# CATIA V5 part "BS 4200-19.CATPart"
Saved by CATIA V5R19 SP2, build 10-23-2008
Part number: BS 4200-19
Bounding box of the stored display mesh (mm): x -47.487 to 47.487, y -47.487 to 47.487, z 0 to 103
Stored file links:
  C:\Users\Bora\Desktop\3D Katı model\BS serisi\BS 4200\BS 4200-19.CATPart
  C:\Program Files\Dassault Systemes\B19\intel_a\reffiles\standard\MetricThickPitch.txt
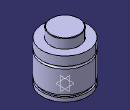
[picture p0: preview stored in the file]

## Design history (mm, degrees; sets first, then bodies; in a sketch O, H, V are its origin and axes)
Body1 (main body)
  Sketch1 on yz-plane, origin (0, 0, 0), H (0, 1, 0), V (0, 0, 1)
    point P2 (47.5, 59.5)
    point P5 (30, 102)
    point P7 (30, 102)
    point P11 (47.5, 64.5)
    point P13 (47.5, 64.5)
    point P14 (47.5, 59.5)
    line L1 (47.5, 13) -> (47.5, 59.5)
    line L2 (44.5, 13) -> (44.5, 8)
    line L3 (30, 102) -> (30, 83)
    arc A1 centre (29, 102) radius 1 from (30, 102) to (29, 103) ccw
    line L4 (47.5, 0) -> (47.5, 8)
    line L5 (47.5, 64.5) -> (47.5, 83)
    arc A2 centre (47.5, 62) radius 2.5 from (47.5, 64.5) to (47.5, 59.5) ccw
    line L6 (29, 103) -> (0, 103)
    point P15 (0, 103)
    line L7 (30, 83) -> (47.5, 83)
    line L8 (0, 0) -> (47.5, 0)
    line L9 (44.5, 13) -> (47.5, 13)
    line L10 (44.5, 8) -> (47.5, 8)
    tangency: L6 A1
    coincidence: P15 V, P2 P14, P5 P7, P11 P13
    horizontal: L7 H, L8 H, L9 H, L10 H
  Shaft1: profile Sketch1, axis Sketch1.V, angle 360
  Sketch2 on face of Shaft1 from Sketch1.L8, origin (0, 0, 0), H (1, 0, 0), V (0, -1, 0)
    point P1 (30, 0)
    distance P1 V = 30
  Hole1: placed by Sketch2, at (30, 0, 0) direction (0, 0, 1), diameter 6.647, depth 7, threaded "M8", thread diameter 8, thread depth 7, pitch 1.25
  CircPattern1: of Hole1, instances 4, angular step 90, axis from xy-plane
